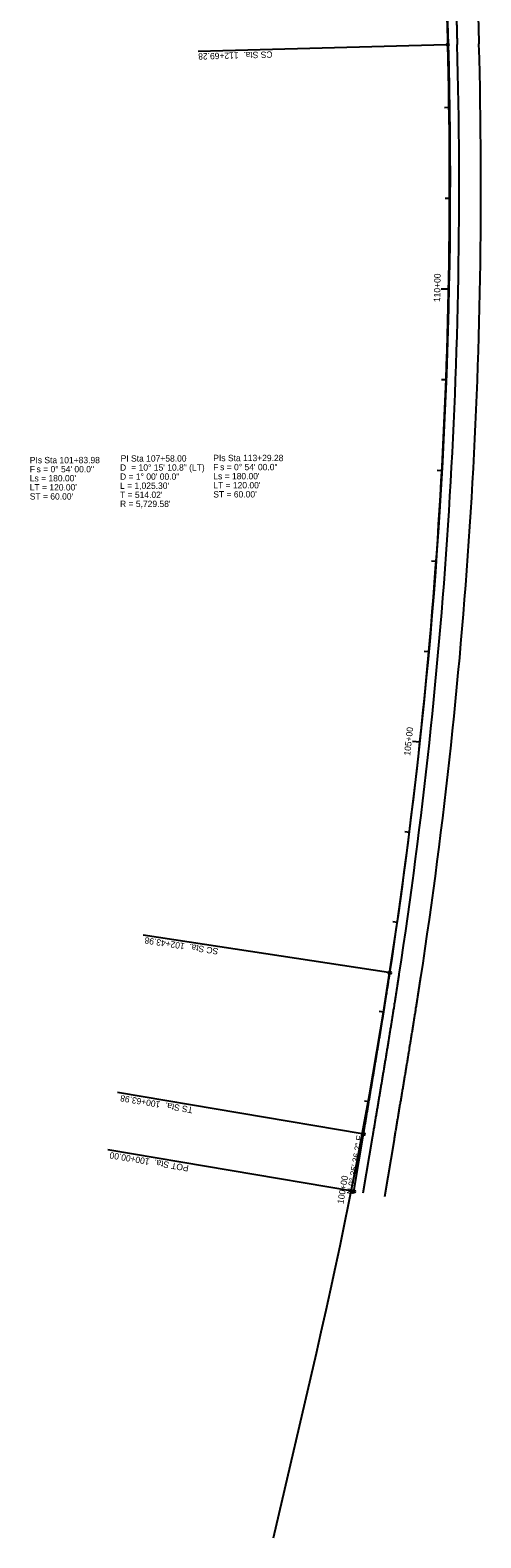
# Model space of a CAD drawing. Extents: x 1722038 to 1726172, y 967033 to 975427.
# Drawn here: x 1723612 to 1724109, y 967033 to 968693 of the extents above; entities that cross this region are included whole.
import ezdxf

# ---------------------------------------------------------------- set-up
doc = ezdxf.new("R2010")
doc.units = 0
for name, color, linetype in [('Prop Horizontal Alignment', 7, 'Continuous'), ('Prop Horizontal Alignment Curve and Spiral Data', 7, 'Continuous'), ('Prop Horizontal Alignment Direction Label', 7, 'Continuous'), ('Prop Horizontal Alignment Station Label', 7, 'Continuous'), ('Prop Horizontal Alignment Tick Label', 7, 'Continuous'), ('Prop Horizontal Alignment Tick Large', 7, 'Continuous'), ('Prop Horizontal Alignment Tick Small', 7, 'Continuous')]:
    doc.layers.add(name, color=color, linetype=linetype)

msp = doc.modelspace()

# ---------------------------------------------------------------- linework, layer by layer
at = {"layer": 'Prop Horizontal Alignment'}
for p, q in [((1723968.6, 967414.1), (1723979.2, 967477.2)), ((1723978.9, 967412.4), (1723989.6, 967475.4)), ((1724002.6, 967408.4), (1724013.3, 967471.4)), ((1723880.1, 967032.6), (1723927.3, 967235.9))]:
    msp.add_line(p, q, dxfattribs=at)
for centre, radius, start, end in [((1718372.4, 968525.3), 5702.6, 346.9318, 2.4976), ((1718344.6, 968520.8), 5729.6, 351.30662, 1.55962), ((1718344.6, 968520.8), 5740.1, 351.30662, 1.55962), ((1718344.6, 968520.8), 5764.1, 351.30662, 1.55962)]:
    msp.add_arc(centre, radius, start, end, dxfattribs=at)
for points in [[(1724065.2, 968856.7), (1724065.3, 968854.2), (1724065.4, 968851.8), (1724065.5, 968849.4), (1724065.7, 968846.9), (1724065.8, 968844.5), (1724065.9, 968842.1), (1724066, 968839.6), (1724066.1, 968837.2), (1724066.2, 968834.8), (1724066.3, 968832.4), (1724066.4, 968829.9), (1724066.5, 968827.5), (1724066.6, 968825.1), (1724066.7, 968822.6), (1724066.8, 968820.2), (1724066.9, 968817.8), (1724067, 968815.3), (1724067.1, 968812.9), (1724067.2, 968810.5), (1724067.3, 968808), (1724067.4, 968805.6), (1724067.5, 968803.2), (1724067.6, 968800.8), (1724067.7, 968798.3), (1724067.8, 968795.9), (1724067.9, 968793.5), (1724068, 968791), (1724068.1, 968788.6), (1724068.2, 968786.2), (1724068.3, 968783.7), (1724068.4, 968781.3), (1724068.5, 968778.9), (1724068.6, 968776.5), (1724068.7, 968774), (1724068.8, 968771.6), (1724068.9, 968769.2), (1724069, 968766.7), (1724069.1, 968764.3), (1724069.2, 968761.9), (1724069.3, 968759.4), (1724069.4, 968757), (1724069.4, 968754.6), (1724069.5, 968752.1), (1724069.6, 968749.7), (1724069.7, 968747.3), (1724069.8, 968744.9), (1724069.9, 968742.4), (1724070, 968740), (1724070.1, 968737.6), (1724070.2, 968735.1), (1724070.3, 968732.7), (1724070.3, 968730.3), (1724070.4, 968727.8), (1724070.5, 968725.4), (1724070.6, 968723), (1724070.7, 968720.5), (1724070.8, 968718.1), (1724070.8, 968715.7), (1724070.9, 968713.3), (1724071, 968710.8), (1724071.1, 968708.4), (1724071.2, 968706), (1724071.2, 968703.5), (1724071.3, 968701.1), (1724071.4, 968698.7), (1724071.5, 968696.2), (1724071.5, 968693.8), (1724071.6, 968691.4), (1724071.7, 968688.9), (1724071.7, 968686.5), (1724071.8, 968684.1), (1724071.9, 968681.6), (1724072, 968679.2), (1724072, 968676.8)], [(1724075.7, 968857.1), (1724075.8, 968854.7), (1724075.9, 968852.2), (1724076, 968849.8), (1724076.1, 968847.4), (1724076.2, 968845), (1724076.4, 968842.5), (1724076.5, 968840.1), (1724076.6, 968837.7), (1724076.7, 968835.2), (1724076.8, 968832.8), (1724076.9, 968830.4), (1724077, 968827.9), (1724077.1, 968825.5), (1724077.2, 968823.1), (1724077.3, 968820.6), (1724077.4, 968818.2), (1724077.5, 968815.8), (1724077.6, 968813.3), (1724077.7, 968810.9), (1724077.8, 968808.5), (1724077.9, 968806.1), (1724078, 968803.6), (1724078.1, 968801.2), (1724078.2, 968798.8), (1724078.3, 968796.3), (1724078.4, 968793.9), (1724078.5, 968791.5), (1724078.6, 968789), (1724078.7, 968786.6), (1724078.8, 968784.2), (1724078.9, 968781.7), (1724079, 968779.3), (1724079.1, 968776.9), (1724079.2, 968774.4), (1724079.3, 968772), (1724079.4, 968769.6), (1724079.5, 968767.1), (1724079.6, 968764.7), (1724079.7, 968762.3), (1724079.8, 968759.8), (1724079.8, 968757.4), (1724079.9, 968755), (1724080, 968752.5), (1724080.1, 968750.1), (1724080.2, 968747.7), (1724080.3, 968745.2), (1724080.4, 968742.8), (1724080.5, 968740.4), (1724080.6, 968737.9), (1724080.7, 968735.5), (1724080.7, 968733.1), (1724080.8, 968730.6), (1724080.9, 968728.2), (1724081, 968725.8), (1724081.1, 968723.3), (1724081.2, 968720.9), (1724081.2, 968718.5), (1724081.3, 968716), (1724081.4, 968713.6), (1724081.5, 968711.2), (1724081.6, 968708.7), (1724081.6, 968706.3), (1724081.7, 968703.9), (1724081.8, 968701.4), (1724081.9, 968699), (1724082, 968696.6), (1724082, 968694.1), (1724082.1, 968691.7), (1724082.2, 968689.2), (1724082.2, 968686.8), (1724082.3, 968684.4), (1724082.4, 968681.9), (1724082.4, 968679.5), (1724082.5, 968677.1)], [(1724099.7, 968858.1), (1724099.8, 968855.7), (1724099.9, 968853.3), (1724100, 968850.8), (1724100.1, 968848.4), (1724100.2, 968846), (1724100.3, 968843.5), (1724100.4, 968841.1), (1724100.5, 968838.7), (1724100.6, 968836.3), (1724100.7, 968833.8), (1724100.8, 968831.4), (1724101, 968829), (1724101.1, 968826.5), (1724101.2, 968824.1), (1724101.3, 968821.7), (1724101.4, 968819.2), (1724101.5, 968816.8), (1724101.6, 968814.4), (1724101.7, 968811.9), (1724101.8, 968809.5), (1724101.9, 968807.1), (1724102, 968804.6), (1724102.1, 968802.2), (1724102.2, 968799.8), (1724102.3, 968797.3), (1724102.4, 968794.9), (1724102.5, 968792.4), (1724102.6, 968790), (1724102.7, 968787.6), (1724102.8, 968785.1), (1724102.9, 968782.7), (1724103, 968780.3), (1724103.1, 968777.8), (1724103.2, 968775.4), (1724103.3, 968773), (1724103.4, 968770.5), (1724103.5, 968768.1), (1724103.5, 968765.6), (1724103.6, 968763.2), (1724103.7, 968760.8), (1724103.8, 968758.3), (1724103.9, 968755.9), (1724104, 968753.4), (1724104.1, 968751), (1724104.2, 968748.6), (1724104.3, 968746.1), (1724104.4, 968743.7), (1724104.5, 968741.2), (1724104.6, 968738.8), (1724104.6, 968736.4), (1724104.7, 968733.9), (1724104.8, 968731.5), (1724104.9, 968729), (1724105, 968726.6), (1724105.1, 968724.2), (1724105.2, 968721.7), (1724105.2, 968719.3), (1724105.3, 968716.8), (1724105.4, 968714.4), (1724105.5, 968711.9), (1724105.6, 968709.5), (1724105.6, 968707.1), (1724105.7, 968704.6), (1724105.8, 968702.2), (1724105.9, 968699.7), (1724105.9, 968697.3), (1724106, 968694.8), (1724106.1, 968692.4), (1724106.2, 968689.9), (1724106.2, 968687.5), (1724106.3, 968685.1), (1724106.4, 968682.6), (1724106.4, 968680.2), (1724106.5, 968677.7)], [(1723979.2, 967477.2), (1723979.7, 967479.6), (1723980.1, 967482), (1723980.5, 967484.4), (1723980.9, 967486.8), (1723981.3, 967489.2), (1723981.7, 967491.6), (1723982.1, 967494), (1723982.5, 967496.4), (1723982.9, 967498.8), (1723983.3, 967501.2), (1723983.7, 967503.6), (1723984.1, 967506), (1723984.5, 967508.4), (1723984.9, 967510.8), (1723985.3, 967513.2), (1723985.7, 967515.6), (1723986.1, 967518), (1723986.5, 967520.4), (1723986.9, 967522.8), (1723987.3, 967525.2), (1723987.7, 967527.6), (1723988.1, 967530), (1723988.5, 967532.4), (1723988.9, 967534.8), (1723989.3, 967537.2), (1723989.7, 967539.6), (1723990.1, 967542), (1723990.5, 967544.4), (1723990.9, 967546.8), (1723991.3, 967549.2), (1723991.7, 967551.6), (1723992.1, 967554), (1723992.5, 967556.4), (1723992.9, 967558.8), (1723993.3, 967561.2), (1723993.7, 967563.6), (1723994.1, 967566), (1723994.5, 967568.4), (1723994.9, 967570.8), (1723995.3, 967573.2), (1723995.7, 967575.6), (1723996.1, 967578), (1723996.5, 967580.4), (1723996.9, 967582.8), (1723997.3, 967585.2), (1723997.7, 967587.6), (1723998.1, 967590), (1723998.5, 967592.4), (1723998.8, 967594.8), (1723999.2, 967597.2), (1723999.6, 967599.6), (1724000, 967602), (1724000.4, 967604.4), (1724000.8, 967606.8), (1724001.2, 967609.2), (1724001.5, 967611.6), (1724001.9, 967614), (1724002.3, 967616.4), (1724002.7, 967618.8), (1724003.1, 967621.2), (1724003.5, 967623.6), (1724003.8, 967626), (1724004.2, 967628.4), (1724004.6, 967630.8), (1724005, 967633.2), (1724005.3, 967635.6), (1724005.7, 967638), (1724006.1, 967640.4), (1724006.5, 967642.8), (1724006.8, 967645.2), (1724007.2, 967647.6), (1724007.6, 967650), (1724007.9, 967652.4), (1724008.3, 967654.8)], [(1723989.6, 967475.4), (1723990, 967477.8), (1723990.4, 967480.2), (1723990.8, 967482.6), (1723991.2, 967485), (1723991.6, 967487.4), (1723992, 967489.8), (1723992.4, 967492.2), (1723992.8, 967494.6), (1723993.2, 967497), (1723993.7, 967499.4), (1723994.1, 967501.8), (1723994.5, 967504.2), (1723994.9, 967506.6), (1723995.3, 967509), (1723995.7, 967511.4), (1723996.1, 967513.8), (1723996.5, 967516.2), (1723996.9, 967518.6), (1723997.3, 967521), (1723997.7, 967523.4), (1723998.1, 967525.8), (1723998.5, 967528.2), (1723998.9, 967530.6), (1723999.3, 967533), (1723999.7, 967535.4), (1724000.1, 967537.8), (1724000.5, 967540.2), (1724000.9, 967542.6), (1724001.3, 967545), (1724001.7, 967547.4), (1724002.1, 967549.8), (1724002.5, 967552.2), (1724002.9, 967554.6), (1724003.3, 967557), (1724003.7, 967559.4), (1724004.1, 967561.8), (1724004.5, 967564.3), (1724004.9, 967566.7), (1724005.3, 967569.1), (1724005.7, 967571.5), (1724006.1, 967573.9), (1724006.5, 967576.3), (1724006.9, 967578.7), (1724007.3, 967581.1), (1724007.6, 967583.5), (1724008, 967585.9), (1724008.4, 967588.3), (1724008.8, 967590.7), (1724009.2, 967593.1), (1724009.6, 967595.5), (1724010, 967597.9), (1724010.4, 967600.3), (1724010.8, 967602.7), (1724011.1, 967605.1), (1724011.5, 967607.5), (1724011.9, 967609.9), (1724012.3, 967612.3), (1724012.7, 967614.7), (1724013.1, 967617.1), (1724013.4, 967619.5), (1724013.8, 967621.9), (1724014.2, 967624.4), (1724014.6, 967626.8), (1724015, 967629.2), (1724015.3, 967631.6), (1724015.7, 967634), (1724016.1, 967636.4), (1724016.5, 967638.8), (1724016.8, 967641.2), (1724017.2, 967643.6), (1724017.6, 967646), (1724018, 967648.4), (1724018.3, 967650.8), (1724018.7, 967653.2)], [(1724013.3, 967471.4), (1724013.7, 967473.8), (1724014.1, 967476.2), (1724014.5, 967478.6), (1724014.9, 967481), (1724015.3, 967483.4), (1724015.7, 967485.8), (1724016.1, 967488.2), (1724016.5, 967490.6), (1724016.9, 967493), (1724017.3, 967495.4), (1724017.7, 967497.8), (1724018.1, 967500.2), (1724018.5, 967502.6), (1724018.9, 967505), (1724019.3, 967507.4), (1724019.7, 967509.9), (1724020.2, 967512.3), (1724020.6, 967514.7), (1724021, 967517.1), (1724021.4, 967519.5), (1724021.8, 967521.9), (1724022.2, 967524.3), (1724022.6, 967526.7), (1724023, 967529.1), (1724023.4, 967531.5), (1724023.8, 967533.9), (1724024.2, 967536.3), (1724024.6, 967538.7), (1724025, 967541.1), (1724025.4, 967543.5), (1724025.8, 967545.9), (1724026.2, 967548.3), (1724026.6, 967550.7), (1724027, 967553.1), (1724027.4, 967555.5), (1724027.8, 967557.9), (1724028.2, 967560.3), (1724028.6, 967562.8), (1724029, 967565.2), (1724029.4, 967567.6), (1724029.8, 967570), (1724030.1, 967572.4), (1724030.5, 967574.8), (1724030.9, 967577.2), (1724031.3, 967579.6), (1724031.7, 967582), (1724032.1, 967584.4), (1724032.5, 967586.8), (1724032.9, 967589.3), (1724033.3, 967591.7), (1724033.7, 967594.1), (1724034.1, 967596.5), (1724034.5, 967598.9), (1724034.8, 967601.3), (1724035.2, 967603.7), (1724035.6, 967606.1), (1724036, 967608.5), (1724036.4, 967611), (1724036.8, 967613.4), (1724037.1, 967615.8), (1724037.5, 967618.2), (1724037.9, 967620.6), (1724038.3, 967623), (1724038.7, 967625.4), (1724039.1, 967627.9), (1724039.4, 967630.3), (1724039.8, 967632.7), (1724040.2, 967635.1), (1724040.6, 967637.5), (1724040.9, 967639.9), (1724041.3, 967642.4), (1724041.7, 967644.8), (1724042, 967647.2), (1724042.4, 967649.6)]]:
    msp.add_spline(points, degree=3, dxfattribs=at)
at = {"layer": 'Prop Horizontal Alignment Station Label'}
for p, q in [((1724070.5, 968676.7), (1723797.1, 968669.3)), ((1724006.8, 967655.1), (1723736.5, 967696.4)), ((1723977.8, 967477.4), (1723708.1, 967523)), ((1723967.1, 967414.4), (1723697.4, 967459.9))]:
    msp.add_line(p, q, dxfattribs=at)
for centre in [(1724072, 968676.8), (1724008.3, 967654.8), (1723979.2, 967477.2), (1723968.6, 967414.1)]:
    msp.add_circle(centre, 1.5, dxfattribs=at)
at = {"layer": 'Prop Horizontal Alignment Tick Large'}
for p, q in [((1724073, 968407.5), (1724065, 968407.7)), ((1724041.3, 967908.7), (1724033.4, 967909.5)), ((1723968.6, 967414.1), (1723960.7, 967415.4))]:
    msp.add_line(p, q, dxfattribs=at)
at = {"layer": 'Prop Horizontal Alignment Tick Small'}
for p, q in [((1724073.5, 968607.5), (1724068.5, 968607.4)), ((1724074.1, 968507.5), (1724069.1, 968507.5)), ((1724070.2, 968307.6), (1724065.2, 968307.8)), ((1724065.6, 968207.7), (1724060.6, 968207.9)), ((1724059.2, 968107.9), (1724054.3, 968108.2)), ((1724051.2, 968008.2), (1724046.2, 968008.7)), ((1724029.8, 967809.4), (1724024.8, 967810)), ((1724016.5, 967710.2), (1724011.6, 967711)), ((1724001.5, 967611.4), (1723996.6, 967612.2)), ((1723985.2, 967512.7), (1723980.3, 967513.5))]:
    msp.add_line(p, q, dxfattribs=at)

# ---------------------------------------------------------------- texts
at = {"layer": 'Prop Horizontal Alignment Curve and Spiral Data'}
for s, p in [('PIs Sta 101+83.98', (1723611.4, 968215.9)), ('PI Sta 107+58.00', (1723711.6, 968217.7)), ('PIs Sta 113+29.28', (1723813.7, 968218.2)), ('F', (1723611.4, 968205.9)), ("Ls = 180.00'", (1723611.4, 968195.9)), ('s = 0%%d 54\' 00.0"', (1723618.9, 968205.9)), ('D', (1723710.9, 968207.7)), ('D = 1%%d 00\' 00.0"', (1723710.9, 968197.7)), ('= 10%%d 15\' 10.8" (LT)', (1723723.3, 968207.8)), ('F', (1723813.7, 968208.2)), ("Ls = 180.00'", (1723813.7, 968198.2)), ('s = 0%%d 54\' 00.0"', (1723821.2, 968208.2)), ("LT = 120.00'", (1723611.4, 968185.9)), ("T = 514.02'", (1723710.9, 968177.7)), ("L = 1,025.30'", (1723710.9, 968187.7)), ("ST = 60.00'", (1723813.7, 968178.2)), ("LT = 120.00'", (1723813.7, 968188.2)), ("ST = 60.00'", (1723611.4, 968175.9)), ("R = 5,729.58'", (1723710.9, 968167.7))]:
    msp.add_text(s, height=7, dxfattribs=at).set_placement(p)
at = {"layer": 'Prop Horizontal Alignment Direction Label'}
msp.add_text('N 9%%d 35\' 36.2" E', height=7, rotation=80.4066, dxfattribs=at).set_placement((1723967.7, 967410.3))
at = {"layer": 'Prop Horizontal Alignment Station Label'}
for s, rotation, p in [('CS Sta.  112+69.28', 181.5596, (1723878.9, 968669.5)), ('SC Sta.  102+43.98', 171.3066, (1723819.6, 967681.7)), ('TS Sta.  100+63.98', 170.4066, (1723791.6, 967506.9)), ('POT Sta.  100+00.00', 170.4066, (1723787, 967442.8))]:
    msp.add_text(s, height=7, rotation=rotation, dxfattribs=at).set_placement(p)
at = {"layer": 'Prop Horizontal Alignment Tick Label'}
for s, rotation, p in [('110+00', 88.8668, (1724063.7, 968393.3)), ('105+00', 83.8668, (1724030.7, 967893.7)), ('100+00', 80.4066, (1723957.1, 967399.9))]:
    msp.add_text(s, height=7, rotation=rotation, dxfattribs=at).set_placement(p)

doc.saveas('drawing.dxf')
